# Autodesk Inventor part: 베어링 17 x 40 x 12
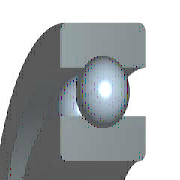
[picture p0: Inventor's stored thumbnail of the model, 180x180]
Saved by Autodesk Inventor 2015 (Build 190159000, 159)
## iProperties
IsCustomPart: 1
Created: 2012-02
Part Number: 베어링 17 x 40 x 12
Material: 강철, 연강
Description: 깊은 그루브 볼 베어링
Document SubType Name: Modeling
Standard: KS B 2023
Designer: mduedu
Standards Organization: KS
Language: ko-KR
Size Designation: 6203 - 17 x 40 x 12
Categories: <MemberInstance><Categories><Category DisplayName="샤프트 부품" InternalName="7f7aeb1f-a693-4053-b835-cee3144e0d98" Mnemonic="SHFT"><Category DisplayName="베어링" Inter
Density: 7.85 g/cm^3
Appearance: 노란색
Mass: 64.8982 g
Surface Area: 64.3582 cm^2
Volume: 8.26729 cm^3
Author: mduedu
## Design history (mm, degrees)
sketch "스케치" dims "d0" = 5.98 (= -0.26 x WD + 0.26 x BD)
  geometry: L1 (3.01, 14.25)-(8.99, 14.25); L2 (6, 14.25)-(6, 11.26); L3 (6, 14.25)-(6, 17.24); L4 (3.778, 12.249)-(0, 12.249); L5 (0, 8.5)-(12, 8.5); L6 (3.778, 16.251)-(0, 16.251); L7 (0, 20)-(12, 20); L8 (12, 8.5)-(12, 12.249); L9 (8.222, 12.249)-(12, 12.249); L10 (8.222, 16.251)-(12, 16.251); L11 (12, 20)-(12, 16.251); L12 (-1.4, 0)-(8.4, 0) reference; L13 (0, -0.3)-(0, 5.3) reference
  constraints: 22 end point, 4 point on line, 2 collinear, 2 perpendicular, 2 symmetric about line, 1 midpoint, 1 parallel, 14 other
  dimensions: "d9" = 17 diameter of L5 L12 (= WD); "d11" = 40 diameter of L7 L12 (= BD); "d12" = 12 distance between parallel lines of L8 L13 (= KB); "d13" = 24.498 diameter of L9 L12 (= 0.326 x BD + 0.674 x WD)
revolve "본체" stored, may be unused: angle "d6" = 90 deg
revolve "볼" stored, may be unused: angle "d7" = 90 deg
pattern_circular "IDS_ARRAYBALL[SIMPL:T]" dims angle "d3" = 360 deg
body "Solid1"
fillet "모깎기1" dims "d1" = 0.6 (= KRS)
other parameters: "WD" = 17 [user parameter; used in 5 equation terms], "BD" = 40 [user parameter; used in 5 equation terms], "KB" = 12 [user parameter; used in 1 equation term], "KRS" = 0.6 [user parameter; used in 1 equation term], "d4" = 0, "d5" = 0, "d8" = 0, "d14" = 0, "d15" = 0, "BBA" = 0 [user parameter], "BC0" = 4750000 [user parameter], "BC" = 9560000 [user parameter], "WR" = 8.5 (= 0.5 x WD) [user parameter]
